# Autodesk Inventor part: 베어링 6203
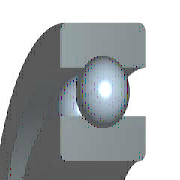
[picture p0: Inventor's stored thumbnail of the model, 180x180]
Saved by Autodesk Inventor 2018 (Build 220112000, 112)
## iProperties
Created: 2012-02
Part Number: 베어링 6203
Material: 강철, 연강
Description: 깊은 그루브 볼 베어링
Document SubType Name: Modeling
Standard: KS B 2023
Designer: mduedu
Standards Organization: KS
Language: ko-KR
Size Designation: 6203 - 17 x 40 x 12
Categories: <MemberInstance><Categories><Category DisplayName="샤프트 부품" InternalName="7f7aeb1f-a693-4053-b835-cee3144e0d98" Mnemonic="SHFT"><Category DisplayName="베어링" Inter
Density: 1 g/cm^3
Appearance: 노란색
IsCustomPart: 1
Author: mduedu
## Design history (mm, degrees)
sketch "스케치" dims "d0" = 5.98 (= -0.26 x WD + 0.26 x BD)
  geometry: L1 (3.01, 14.25)-(8.99, 14.25); L2 (6, 14.25)-(6, 11.26); L3 (6, 14.25)-(6, 17.24); L4 (3.778, 12.249)-(0, 12.249); L5 (0, 8.5)-(12, 8.5); L6 (3.778, 16.251)-(0, 16.251); L7 (0, 20)-(12, 20); L8 (12, 8.5)-(12, 12.249); L9 (8.222, 12.249)-(12, 12.249); L10 (8.222, 16.251)-(12, 16.251); L11 (12, 20)-(12, 16.251); L12 (-1.4, 0)-(8.4, 0) reference; L13 (0, -0.3)-(0, 5.3) reference
  constraints: 22 end point, 4 point on line, 2 collinear, 2 perpendicular, 2 symmetric about line, 1 midpoint, 1 parallel, 14 other
  dimensions: "d9" = 17 diameter of L5 L12 (= WD); "d11" = 40 diameter of L7 L12 (= BD); "d12" = 12 distance between parallel lines of L8 L13 (= KB); "d13" = 24.498 diameter of L9 L12 (= 0.326 x BD + 0.674 x WD)
revolve "본체" stored, may be unused: angle "d6" = 90 deg
revolve "볼" stored, may be unused: angle "d7" = 90 deg
pattern_circular "IDS_ARRAYBALL[SIMPL:T]" dims angle "d3" = 360 deg
body "Solid1"
fillet "모깎기1" dims "d1" = 0.6 (= KRS)
other parameters: "WD" = 17 [user parameter; used in 5 equation terms], "BD" = 40 [user parameter; used in 5 equation terms], "KB" = 12 [user parameter; used in 1 equation term], "KRS" = 0.6 [user parameter; used in 1 equation term], "d4" = 0, "d5" = 0, "d8" = 0, "d14" = 0, "d15" = 0, "BBA" = 0 [user parameter], "BC0" = 4750000 [user parameter], "BC" = 9560000 [user parameter], "WR" = 8.5 (= 0.5 x WD) [user parameter]
